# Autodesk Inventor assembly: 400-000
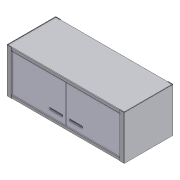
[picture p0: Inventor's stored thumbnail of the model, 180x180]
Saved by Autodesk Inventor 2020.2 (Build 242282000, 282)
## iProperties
Created: 2010-10
Part Number: 400-000
Document SubType Name: Assembly
Designer: F.Stasiak
Description: =Szafka sterownicza S:<d26> x W:<d27>
Company: Fabian Stasiak CAD Consulting
Manager: www.cadconsulting.pl
d26: 1200
d27: 450
Author: F.Stasiak
Subject: Zbiór ćwiczeń. Autodesk Inventor 2020. Kurs podstawowy
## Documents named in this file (6)
- C:\2020_Kurs_podstawowy\R9 Zarządzanie plikami\400-000\400-000.iam
- C:\2020_Kurs_podstawowy\R9 Zarządzanie plikami\500-000\500-100.ipt
- C:\2020_Kurs_podstawowy\R9 Zarządzanie plikami\400-000\400-200.ipt
- C:\2020_Kurs_podstawowy\R9 Zarządzanie plikami\400-000\400-300.ipt
- C:\2020_Kurs_podstawowy\R9 Zarządzanie plikami\500-000\500-400.ipt
- C:\2020_Kurs_podstawowy\R9 Zarządzanie plikami\400-000\400-500.ipt
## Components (6 placed, 5 different names)
1. 500-100:1 — Zestawiający:1, Zestawiający:2, Równoległy:5, Równoległy:6, Zestawiający:3, Zestawiający:6, Zestawiający:9
2. 400-200:1 — Równoległy:4, Zestawiający:1, Równoległy:5, Równoległy:7, Zestawiający:7, Równoległy:8
3. 400-300:1 — Równoległy:4, Zestawiający:2, Równoległy:6, Zestawiający:3, Zestawiający:4, Zestawiający:5, Zestawiający:10
4. 500-400:1 — Równoległy:7, Zestawiający:4, Zestawiający:5, Zestawiający:8
5. 400-500:1 — Zestawiający:6, Zestawiający:7, Równoległy:8, Zestawiający:8, Równoległy:9
6. 400-500:2 — Zestawiający:9, Zestawiający:10, Równoległy:9
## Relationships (16: Mate 10, Flush 6)
- Równoległy:4 [Flush]: 400-200:1 ↔ 400-300:1
- Zestawiający:1 [Mate]: 500-100:1 ↔ 400-200:1
- Zestawiający:2 [Mate]: 500-100:1 ↔ 400-300:1
- Równoległy:5 [Flush]: 500-100:1 ↔ 400-200:1
- Równoległy:6 [Flush]: 500-100:1 ↔ 400-300:1
- Zestawiający:3 [Mate]: 500-100:1 ↔ 400-300:1
- Równoległy:7 [Flush]: 400-200:1 ↔ 500-400:1
- Zestawiający:4 [Mate]: 400-300:1 ↔ 500-400:1
- Zestawiający:5 [Mate]: 400-300:1 ↔ 500-400:1
- Zestawiający:6 [Mate]: 500-100:1 ↔ 400-500:1
- Zestawiający:7 [Mate]: 400-200:1 ↔ 400-500:1
- Równoległy:8 [Flush]: 400-200:1 ↔ 400-500:1
- Zestawiający:8 [Mate]: 500-400:1 ↔ 400-500:1
- Zestawiający:9 [Mate]: 500-100:1 ↔ 400-500:2
- Zestawiający:10 [Mate]: 400-300:1 ↔ 400-500:2
- Równoległy:9 [Flush]: 400-500:1 ↔ 400-500:2
